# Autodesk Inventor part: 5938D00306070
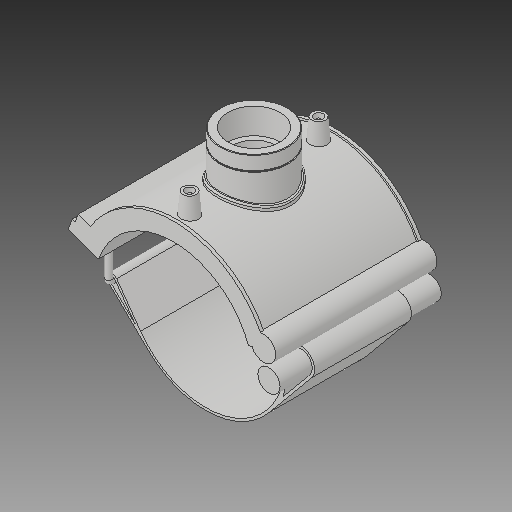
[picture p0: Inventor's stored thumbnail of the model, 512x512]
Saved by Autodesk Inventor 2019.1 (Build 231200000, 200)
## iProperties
Created: 2017-07
Part Number: 5938D00306070
Material: Generic
Description: PLASSON TRANSITION SADDLE 6''DIPS x 2"NPT
Document SubType Name: Modeling
Designer: KIM
Density: 1 g/cm^3
Appearance: Default
Author: KIM
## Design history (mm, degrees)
derived "5938D.ipt"
feature "Solid1::5938D.ipt"
tag "TaggingFeature1"
body "Solid1"
other parameters: "d0" = 174.5, "d1" = 209.4, "d2" = 441.96, "d3" = 43.625, "d4" = 176.022, "d5" = 0, "d40" = 108.888, "d41" = 79.3184, "d43" = 0, "d45" = 0, "d47" = 151.436, "d48" = 73.6528, "d50" = 0, "d78" = 126.7, "d79" = 15, "d80" = 70.4088, "d82" = 5 deg, "d84" = 4, "d85" = 14, "d86" = 0, "d87" = 3, "d88" = 0, "d96" = 213.588, "d97" = 3.52044, "d98" = 0, "d102" = 1.69968, "d103" = 56.656, "d104" = 28.0416, "d105" = 0, "d106" = 45.3248, "d108" = 0, "d109" = -15.57867, "d111" = 0.5, "d112" = 0.5, "d113" = 0, "d114" = 0.5, "d117" = 0.56656, "d120" = 140 deg, "d121" = 24.228, "d122" = 20 deg, "d123" = 837.6, "d124" = 125.64, "d126" = 0, "d143" = 179.735, "d145" = 26.84615, "d149" = 2.6175, "d150" = 29.53077, "d153" = 176.022, "d154" = 0, "d156" = 104.7, "d157" = 160 deg, "d159" = 6.98, "d161" = 2.6175, "d162" = 105.6132, "d163" = 0, "d164" = 87.25, "d167" = 17.45, "d168" = 102.14634, "d170" = 2.6175, "d172" = 0, "d173" = 1, "d175" = 87.25, "d176" = 20 deg, "d177" = 12.215, "d178" = 34.9, "d180" = 0, "d183" = 13.96, "d184" = 9.772, "d185" = 57.20715, "d186" = 57.20715, "d187" = 104.7, "d188" = 10.47, "d189" = 12.215, "d190" = 0, "d191" = 125.64, "d193" = 6.98, "d194" = 3.57725, "d195" = 90 deg, "d197" = 0, "d199" = 0, "d_" = 174.5, "B_" = 176.784, "H_" = 46.736, "L_" = 176.022, "d_t" = 6, "G_" = 56.656, "d148" = 2.6175, "d160" = 2.6175, "d169" = 2.6175, "d192" = 6.98
